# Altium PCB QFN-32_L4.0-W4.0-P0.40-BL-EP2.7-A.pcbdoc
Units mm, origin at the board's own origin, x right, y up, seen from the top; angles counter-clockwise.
Board outline 17.1 x 17.49 mm, 2 copper layers (Top Layer, Bottom Layer), stack 0 mm thick; 1 components, 0 nets, 33 pads, 0 vias.
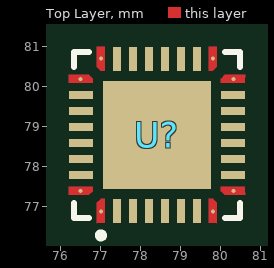
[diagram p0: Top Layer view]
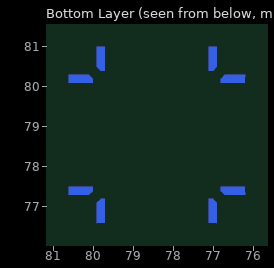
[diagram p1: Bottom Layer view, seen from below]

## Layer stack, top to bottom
Top Layer: signal copper (thickness not stored)
Bottom Layer: signal copper (thickness not stored)

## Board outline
86.951,69.85 69.85,69.85 69.85,87.336 86.951,87.336

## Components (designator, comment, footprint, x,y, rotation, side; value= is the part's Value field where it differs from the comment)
U? "" QFN-32_L4.0-W4.0-P0.40-BL-EP2.7-A 78.401,78.785 r0 top

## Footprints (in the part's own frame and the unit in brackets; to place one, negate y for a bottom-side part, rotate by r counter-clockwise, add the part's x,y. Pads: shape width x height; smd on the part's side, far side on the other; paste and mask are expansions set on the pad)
QFN-32_L4.0-W4.0-P0.40-BL-EP2.7-A [mm]
  round 0.097 smd: 1(-1.397,-1.912) 8(1.397,-1.912) 9(1.912,-1.397) 16(1.912,1.397) 17(1.397,1.912) 24(-1.397,1.912) 25(-1.912,1.397) 32(-1.912,-1.397)
  rect 0.2x0.6 smd paste-100 mask+0.05: 2(-1,-1.9) 3(-0.6,-1.9) 4(-0.2,-1.9) 5(0.2,-1.9) 6(0.6,-1.9) 7(1,-1.9) 18(1,1.9) 19(0.6,1.9) 20(0.2,1.9) 21(-0.2,1.9) 22(-0.6,1.9) 23(-1,1.9)
  rect 0.6x0.2 smd paste-100 mask+0.05: 10(1.9,-1) 11(1.9,-0.6) 12(1.9,-0.2) 13(1.9,0.2) 14(1.9,0.6) 15(1.9,1) 26(-1.9,1) 27(-1.9,0.6) 28(-1.9,0.2) 29(-1.9,-0.2) 30(-1.9,-0.6) 31(-1.9,-1)
  rect 2.7x2.7 smd paste-100 mask+0.05: 33(0,0)
  Top Layer region: -1.375,2.2 -1.5,2.201 -1.5,1.7 -1.401,1.601 -1.401,1.6 -1.3,1.6 -1.3,2.2
  Top Layer region: -2.201,1.5 -1.7,1.5 -1.601,1.401 -1.6,1.401 -1.6,1.3 -2.2,1.3 -2.2,1.375
  Top Layer region: 1.5,2.201 1.5,1.7 1.4,1.601 1.4,1.6 1.3,1.6 1.3,2.2 1.374,2.2
  Top Layer region: 2.201,1.5 1.7,1.5 1.601,1.4 1.6,1.4 1.6,1.3 2.2,1.3 2.2,1.374
  Top Layer region: 2.201,-1.5 1.7,-1.5 1.601,-1.401 1.6,-1.401 1.6,-1.3 2.2,-1.3 2.2,-1.375
  Top Layer region: 1.5,-2.201 1.5,-1.7 1.401,-1.601 1.401,-1.6 1.3,-1.6 1.3,-2.2 1.375,-2.2
  Top Layer region: -1.5,-2.201 -1.5,-1.7 -1.401,-1.601 -1.401,-1.6 -1.3,-1.6 -1.3,-2.2 -1.375,-2.2
  Top Layer region: -2.201,-1.5 -1.7,-1.5 -1.601,-1.401 -1.6,-1.401 -1.6,-1.3 -2.2,-1.3 -2.2,-1.375
  Bottom Layer region: -1.375,2.2 -1.5,2.201 -1.5,1.7 -1.401,1.601 -1.401,1.6 -1.3,1.6 -1.3,2.2
  Bottom Layer region: -2.201,1.5 -1.7,1.5 -1.601,1.401 -1.6,1.401 -1.6,1.3 -2.2,1.3 -2.2,1.375
  Bottom Layer region: 1.5,2.201 1.5,1.7 1.4,1.601 1.4,1.6 1.3,1.6 1.3,2.2 1.374,2.2
  Bottom Layer region: 2.201,1.5 1.7,1.5 1.601,1.4 1.6,1.4 1.6,1.3 2.2,1.3 2.2,1.374
  Bottom Layer region: 2.201,-1.5 1.7,-1.5 1.601,-1.401 1.6,-1.401 1.6,-1.3 2.2,-1.3 2.2,-1.375
  Bottom Layer region: 1.5,-2.201 1.5,-1.7 1.401,-1.601 1.401,-1.6 1.3,-1.6 1.3,-2.2 1.375,-2.2
  Bottom Layer region: -1.5,-2.201 -1.5,-1.7 -1.401,-1.601 -1.401,-1.6 -1.3,-1.6 -1.3,-2.2 -1.375,-2.2
  Bottom Layer region: -2.201,-1.5 -1.7,-1.5 -1.601,-1.401 -1.6,-1.401 -1.6,-1.3 -2.2,-1.3 -2.2,-1.375
  Multi-Layer region: -1.375,2.2 -1.5,2.201 -1.5,1.7 -1.401,1.601 -1.401,1.6 -1.3,1.6 -1.3,2.2
  Multi-Layer region: -2.201,1.5 -1.7,1.5 -1.601,1.401 -1.6,1.401 -1.6,1.3 -2.2,1.3 -2.2,1.375
  Multi-Layer region: 1.5,2.201 1.5,1.7 1.4,1.601 1.4,1.6 1.3,1.6 1.3,2.2 1.374,2.2
  Multi-Layer region: 2.201,1.5 1.7,1.5 1.601,1.4 1.6,1.4 1.6,1.3 2.2,1.3 2.2,1.374
  Multi-Layer region: 2.201,-1.5 1.7,-1.5 1.601,-1.401 1.6,-1.401 1.6,-1.3 2.2,-1.3 2.2,-1.375
  Multi-Layer region: 1.5,-2.201 1.5,-1.7 1.401,-1.601 1.401,-1.6 1.3,-1.6 1.3,-2.2 1.375,-2.2
  Multi-Layer region: -1.5,-2.201 -1.5,-1.7 -1.401,-1.601 -1.401,-1.6 -1.3,-1.6 -1.3,-2.2 -1.375,-2.2
  Multi-Layer region: -2.201,-1.5 -1.7,-1.5 -1.601,-1.401 -1.6,-1.401 -1.6,-1.3 -2.2,-1.3 -2.2,-1.375
  silkscreen extent -2.08,-2.58 2.08,2.08

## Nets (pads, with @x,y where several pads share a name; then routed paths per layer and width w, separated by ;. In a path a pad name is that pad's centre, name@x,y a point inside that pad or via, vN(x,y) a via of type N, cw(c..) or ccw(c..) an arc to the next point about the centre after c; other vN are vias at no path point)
pads on no net: U?.1 U?.2 U?.3 U?.4 U?.5 U?.6 U?.7 U?.8 U?.9 U?.10 U?.11 U?.12 U?.13 U?.14 U?.15 U?.16 U?.17 U?.18 U?.19 U?.20 U?.21 U?.22 U?.23 U?.24 U?.25 U?.26 U?.27 U?.28 U?.29 U?.30 U?.31 U?.32 U?.33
